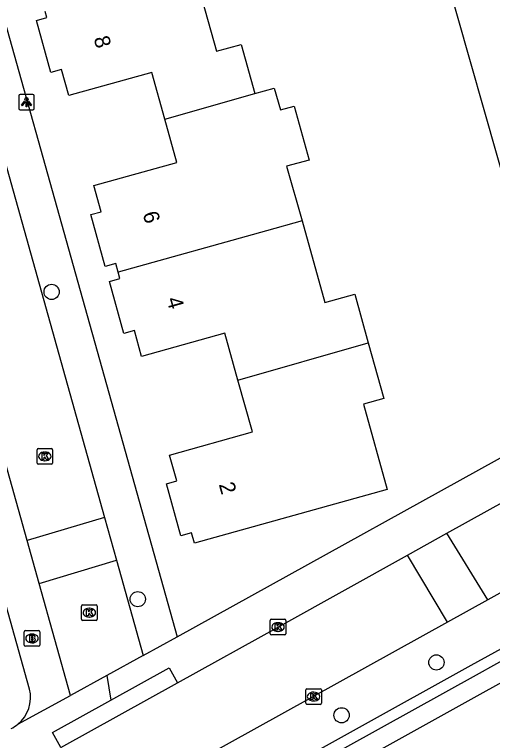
# Model space of a CAD drawing. Extents: x 159628 to 160723, y 388176 to 389416.
# Drawn here: x 160064 to 160094.67, y 388427.86 to 388474.45 of the extents above; entities that cross this region are included whole.
import ezdxf

# ---------------------------------------------------------------- set-up
doc = ezdxf.new("R2010")
doc.units = 0
for name, color, linetype in [('IMGEO_Boom', 7, 'Continuous'), ('IMGEO_Brandkraan', 7, 'Continuous'), ('IMGEO_Groenvoorziening', 7, 'Continuous'), ('IMGEO_Haag', 7, 'Continuous'), ('IMGEO_Kolk', 7, 'Continuous'), ('IMGEO_Lichtpunt', 7, 'Continuous'), ('IMGEO_Muur', 7, 'Continuous'), ('IMGEO_Pand', 7, 'Continuous'), ('IMGEO_Pand_nummerreeks', 7, 'Continuous'), ('IMGEO_Rijbaan_lokaal_open', 7, 'Continuous'), ('IMGEO_Voetpad_open', 7, 'Continuous')]:
    doc.layers.add(name, color=color, linetype=linetype)

msp = doc.modelspace()

# ---------------------------------------------------------------- linework, layer by layer
at = {"layer": 'IMGEO_Boom'}
for centre in [(160066.378, 388456.646), (160071.906, 388436.928), (160091.07, 388432.869), (160084.986, 388429.476)]:
    msp.add_circle(centre, 0.489, dxfattribs=at)
at = {"layer": 'IMGEO_Brandkraan'}
for p, q in [((160064.617, 388433.981), (160064.617, 388434.833)), ((160064.692, 388434.907), (160065.544, 388434.907)), ((160065.105, 388434.687), (160065.13, 388434.687)), ((160065.618, 388434.833), (160065.618, 388433.981)), ((160065.544, 388433.907), (160064.692, 388433.907)), ((160065.128, 388434.127), (160065.103, 388434.127))]:
    msp.add_line(p, q, dxfattribs=at)
for points in [[(160064.617, 388433.981), (160064.617, 388434.833)], [(160064.692, 388434.907), (160065.544, 388434.907)], [(160064.965, 388434.607), (160064.965, 388434.207), (160065.178, 388434.207)], [(160065.196, 388434.607), (160064.965, 388434.607)], [(160065.618, 388434.833), (160065.618, 388433.981)], [(160065.144, 388434.526), (160065.09, 388434.526), (160065.09, 388434.45)], [(160065.09, 388434.45), (160065.143, 388434.45)], [(160065.152, 388434.374), (160065.09, 388434.374), (160065.09, 388434.293)], [(160065.09, 388434.293), (160065.152, 388434.293)], [(160065.544, 388433.907), (160064.692, 388433.907)]]:
    msp.add_lwpolyline(points, dxfattribs=at)
for centre, radius, start, end in [((160064.694, 388434.831), 0.0765, 91.552, 178.448), ((160064.694, 388434.831), 0.0765, 91.552, 178.448), ((160065.2, 388434.462), 0.145, 59.4692, 91.5367), ((160065.542, 388434.831), 0.0765, 1.552, 88.448), ((160065.542, 388434.831), 0.0765, 1.552, 88.448), ((160065.145, 388434.488), 0.0379, 267.8285, 90.9355), ((160065.153, 388434.333), 0.0404, 269.8759, 90.5077), ((160065.184, 388434.458), 0.251, 268.6676, 293.5347), ((160065.225, 388434.509), 0.0922, 285.5137, 58.1501), ((160065.23, 388434.317), 0.105, 301.3115, 78.989), ((160064.694, 388433.983), 0.0765, 181.552, 268.448), ((160064.694, 388433.983), 0.0765, 181.552, 268.448), ((160065.542, 388433.983), 0.0765, 271.552, 358.448), ((160065.542, 388433.983), 0.0765, 271.552, 358.448)]:
    msp.add_arc(centre, radius, start, end, dxfattribs=at)
for centre, major_axis, ratio, start_param, end_param in [((160065.104, 388434.407), (-0.387, 0.002), 0.722429, 4.712389, 7.853982), ((160065.129, 388434.407), (-0.39, 0.002), 0.717154, 1.570796, 4.712389)]:
    msp.add_ellipse(centre, major_axis=major_axis, ratio=ratio, start_param=start_param, end_param=end_param, dxfattribs=at)
at = {"layer": 'IMGEO_Groenvoorziening'}
msp.add_lwpolyline([(160134.059, 388453.138), (160126.17, 388448.757), (160071.823, 388418.575), (160075.33, 388405.904)], dxfattribs=at)
at = {"layer": 'IMGEO_Haag'}
for points in [[(160070.833, 388420.227), (160093.307, 388432.688), (160095.907, 388434.13), (160127.052, 388451.4), (160127.514, 388451.656), (160133.566, 388454.936)], [(160071.028, 388419.535), (160093.647, 388432.076), (160096.247, 388433.518), (160127.392, 388450.788), (160127.85, 388451.042), (160133.756, 388454.242)]]:
    msp.add_lwpolyline(points, dxfattribs=at)
at = {"layer": 'IMGEO_Kolk'}
for p, q in [((160065.442, 388445.667), (160065.442, 388446.519)), ((160065.517, 388446.593), (160066.369, 388446.593)), ((160065.93, 388446.373), (160065.955, 388446.373)), ((160066.443, 388446.519), (160066.443, 388445.667)), ((160065.953, 388445.813), (160065.928, 388445.813)), ((160066.369, 388445.593), (160065.517, 388445.593)), ((160068.3, 388435.637), (160068.3, 388436.489)), ((160068.375, 388436.563), (160069.227, 388436.563)), ((160069.301, 388436.489), (160069.301, 388435.637)), ((160068.788, 388436.343), (160068.813, 388436.343)), ((160069.227, 388435.563), (160068.375, 388435.563)), ((160068.811, 388435.783), (160068.786, 388435.783)), ((160080.407, 388434.712), (160080.407, 388435.564)), ((160080.482, 388435.638), (160081.334, 388435.638)), ((160081.408, 388435.564), (160081.408, 388434.712)), ((160080.895, 388435.418), (160080.92, 388435.418)), ((160081.334, 388434.638), (160080.482, 388434.638)), ((160080.918, 388434.858), (160080.893, 388434.858)), ((160082.687, 388430.253), (160082.687, 388431.105)), ((160082.762, 388431.179), (160083.614, 388431.179)), ((160083.175, 388430.959), (160083.2, 388430.959)), ((160083.688, 388431.105), (160083.688, 388430.253)), ((160083.614, 388430.179), (160082.762, 388430.179)), ((160083.198, 388430.399), (160083.173, 388430.399))]:
    msp.add_line(p, q, dxfattribs=at)
for points in [[(160065.442, 388445.667), (160065.442, 388446.519)], [(160065.517, 388446.593), (160066.369, 388446.593)], [(160065.763, 388446.293), (160065.886, 388446.293), (160065.886, 388446.142), (160066.016, 388446.293), (160066.18, 388446.293), (160066.034, 388446.142), (160066.187, 388445.893), (160066.035, 388445.893), (160065.95, 388446.057), (160065.886, 388445.99), (160065.886, 388445.893), (160065.763, 388445.893), (160065.763, 388446.293)], [(160066.443, 388446.519), (160066.443, 388445.667)], [(160066.369, 388445.593), (160065.517, 388445.593)], [(160068.3, 388435.637), (160068.3, 388436.489)], [(160068.375, 388436.563), (160069.227, 388436.563)], [(160069.301, 388436.489), (160069.301, 388435.637)], [(160068.621, 388436.263), (160068.744, 388436.263), (160068.744, 388436.112), (160068.874, 388436.263), (160069.038, 388436.263), (160068.892, 388436.112), (160069.045, 388435.863), (160068.893, 388435.863), (160068.808, 388436.027), (160068.744, 388435.96), (160068.744, 388435.863), (160068.621, 388435.863), (160068.621, 388436.263)], [(160069.227, 388435.563), (160068.375, 388435.563)], [(160080.407, 388434.712), (160080.407, 388435.564)], [(160080.482, 388435.638), (160081.334, 388435.638)], [(160081.408, 388435.564), (160081.408, 388434.712)], [(160080.728, 388435.338), (160080.851, 388435.338), (160080.851, 388435.187), (160080.981, 388435.338), (160081.145, 388435.338), (160080.999, 388435.187), (160081.152, 388434.938), (160081, 388434.938), (160080.915, 388435.102), (160080.851, 388435.035), (160080.851, 388434.938), (160080.728, 388434.938), (160080.728, 388435.338)], [(160081.334, 388434.638), (160080.482, 388434.638)], [(160082.687, 388430.253), (160082.687, 388431.105)], [(160082.762, 388431.179), (160083.614, 388431.179)], [(160083.008, 388430.879), (160083.131, 388430.879), (160083.131, 388430.728), (160083.261, 388430.879), (160083.425, 388430.879), (160083.279, 388430.728), (160083.432, 388430.479), (160083.28, 388430.479), (160083.195, 388430.643), (160083.131, 388430.576), (160083.131, 388430.479), (160083.008, 388430.479), (160083.008, 388430.879)], [(160083.688, 388431.105), (160083.688, 388430.253)], [(160083.614, 388430.179), (160082.762, 388430.179)]]:
    msp.add_lwpolyline(points, dxfattribs=at)
for centre, start, end in [((160065.519, 388446.517), 91.552, 178.448), ((160065.519, 388446.517), 91.552, 178.448), ((160066.367, 388446.517), 1.552, 88.448), ((160066.367, 388446.517), 1.552, 88.448), ((160065.519, 388445.669), 181.552, 268.448), ((160065.519, 388445.669), 181.552, 268.448), ((160066.367, 388445.669), 271.552, 358.448), ((160066.367, 388445.669), 271.552, 358.448), ((160068.377, 388436.487), 91.552, 178.448), ((160068.377, 388436.487), 91.552, 178.448), ((160069.225, 388436.487), 1.552, 88.448), ((160069.225, 388436.487), 1.552, 88.448), ((160068.377, 388435.639), 181.552, 268.448), ((160068.377, 388435.639), 181.552, 268.448), ((160069.225, 388435.639), 271.552, 358.448), ((160069.225, 388435.639), 271.552, 358.448), ((160080.484, 388435.562), 91.552, 178.448), ((160080.484, 388435.562), 91.552, 178.448), ((160081.332, 388435.562), 1.552, 88.448), ((160081.332, 388435.562), 1.552, 88.448), ((160080.484, 388434.714), 181.552, 268.448), ((160080.484, 388434.714), 181.552, 268.448), ((160081.332, 388434.714), 271.552, 358.448), ((160081.332, 388434.714), 271.552, 358.448), ((160082.764, 388431.103), 91.552, 178.448), ((160082.764, 388431.103), 91.552, 178.448), ((160083.612, 388431.103), 1.552, 88.448), ((160083.612, 388431.103), 1.552, 88.448), ((160082.764, 388430.255), 181.552, 268.448), ((160082.764, 388430.255), 181.552, 268.448), ((160083.612, 388430.255), 271.552, 358.448), ((160083.612, 388430.255), 271.552, 358.448)]:
    msp.add_arc(centre, 0.0765, start, end, dxfattribs=at)
for centre, major_axis, ratio, start_param, end_param in [((160065.929, 388446.093), (-0.387, 0.002), 0.722429, 4.712389, 7.853982), ((160065.954, 388446.093), (-0.39, 0.002), 0.717154, 1.570796, 4.712389), ((160068.787, 388436.063), (-0.387, 0.002), 0.722429, 4.712389, 7.853982), ((160068.812, 388436.063), (-0.39, 0.002), 0.717154, 1.570796, 4.712389), ((160080.894, 388435.138), (-0.387, 0.002), 0.722429, 4.712389, 7.853982), ((160080.919, 388435.138), (-0.39, 0.002), 0.717154, 1.570796, 4.712389), ((160083.174, 388430.679), (-0.387, 0.002), 0.722429, 4.712389, 7.853982), ((160083.199, 388430.679), (-0.39, 0.002), 0.717154, 1.570796, 4.712389)]:
    msp.add_ellipse(centre, major_axis=major_axis, ratio=ratio, start_param=start_param, end_param=end_param, dxfattribs=at)
at = {"layer": 'IMGEO_Lichtpunt'}
for p, q in [((160064.268, 388469.225), (160064.268, 388468.418)), ((160064.268, 388469.225), (160064.268, 388468.418)), ((160065.17, 388469.32), (160064.362, 388469.32)), ((160065.17, 388469.32), (160064.362, 388469.32)), ((160065.264, 388468.418), (160065.264, 388469.225)), ((160065.264, 388468.418), (160065.264, 388469.225)), ((160064.362, 388468.324), (160065.17, 388468.324)), ((160064.362, 388468.324), (160065.17, 388468.324))]:
    msp.add_line(p, q, dxfattribs=at)
for points in [[(160064.642, 388468.889), (160064.681, 388468.861), (160064.493, 388468.599), (160064.455, 388468.626), (160064.642, 388468.889)], [(160064.744, 388468.841), (160064.791, 388468.841), (160064.791, 388468.519), (160064.744, 388468.519), (160064.744, 388468.841)], [(160064.854, 388468.861), (160064.892, 388468.888), (160065.079, 388468.626), (160065.04, 388468.598), (160064.854, 388468.861)]]:
    msp.add_lwpolyline(points, dxfattribs=at)
msp.add_circle((160064.767, 388469.023), 0.0994, dxfattribs=at)
for centre, start, end in [((160064.362, 388469.225), 90, 180), ((160064.362, 388469.225), 90, 180), ((160065.17, 388469.225), 0, 90), ((160065.17, 388469.225), 0, 90), ((160064.362, 388468.418), 180, 270), ((160064.362, 388468.418), 180, 270), ((160065.17, 388468.418), 270, 0), ((160065.17, 388468.418), 270, 360)]:
    msp.add_arc(centre, 0.0946, start, end, dxfattribs=at)
at = {"layer": 'IMGEO_Muur'}
msp.add_lwpolyline([(160097.525, 388456.458), (160084.795, 388501.192)], dxfattribs=at)
at = {"layer": 'IMGEO_Pand'}
for points in [[(160075.509, 388477.292), (160076.957, 388472.092), (160078.547, 388472.535), (160079.425, 388469.382)], [(160073.636, 388467.739), (160072.804, 388470.727), (160067.476, 388469.244), (160067.01, 388470.919), (160066.335, 388470.731), (160065.407, 388474.062), (160066.081, 388474.249), (160065.973, 388474.634)], [(160079.425, 388469.382), (160080.669, 388469.728), (160081.066, 388468.334), (160081.933, 388468.575), (160082.898, 388465.107), (160081.451, 388464.711), (160082.452, 388461.218)], [(160073.636, 388467.739), (160079.425, 388469.382)], [(160070.642, 388457.914), (160070.489, 388458.463), (160069.815, 388458.275), (160068.887, 388461.606), (160069.561, 388461.793), (160069.092, 388463.478), (160074.41, 388464.957), (160073.636, 388467.739)], [(160082.452, 388461.218), (160080.163, 388460.578), (160070.642, 388457.914)], [(160082.452, 388461.218), (160083.914, 388455.969), (160085.825, 388456.501), (160086.695, 388453.375)], [(160078.336, 388450.985), (160077.49, 388453.996), (160072.153, 388452.496), (160071.687, 388454.171), (160071.012, 388453.983), (160070.084, 388457.314), (160070.758, 388457.501), (160070.642, 388457.914)], [(160086.695, 388453.375), (160087.689, 388449.806), (160086.389, 388449.445), (160087.916, 388443.96), (160075.543, 388440.516), (160075.353, 388441.189), (160074.679, 388440.999), (160073.743, 388444.33), (160074.416, 388444.519), (160073.951, 388446.174), (160079.268, 388447.667), (160078.336, 388450.985)], [(160078.336, 388450.985), (160086.695, 388453.375)]]:
    msp.add_lwpolyline(points, dxfattribs=at)
at = {"layer": 'IMGEO_Rijbaan_lokaal_open'}
for points in [[(160099.774, 388448.551), (160097.525, 388456.458), (160084.795, 388501.192)], [(160055.946, 388491.534), (160069.781, 388442.163)], [(160064.814, 388440.692), (160050.975, 388490.162)], [(160132.71, 388458.055), (160126, 388454.418), (160094.379, 388436.885)], [(160091.748, 388441.158), (160099.494, 388445.461)], [(160069.781, 388442.163), (160064.814, 388440.692)], [(160069.781, 388442.163), (160070.546, 388439.435)], [(160089.213, 388439.75), (160091.748, 388441.158)], [(160094.379, 388436.885), (160091.748, 388441.158)], [(160065.586, 388437.929), (160064.814, 388440.692)], [(160074.447, 388431.557), (160081.031, 388435.205), (160089.213, 388439.75)], [(160091.779, 388435.443), (160089.213, 388439.75)], [(160065.586, 388437.929), (160070.546, 388439.435)], [(160070.546, 388439.435), (160072.262, 388433.311)], [(160067.596, 388430.745), (160065.586, 388437.929)], [(160094.379, 388436.885), (160091.779, 388435.443)], [(160091.779, 388435.443), (160070.678, 388423.743)], [(160072.262, 388433.311), (160069.929, 388432.028)], [(160070.172, 388430.447), (160073.914, 388432.519), (160074.447, 388431.557)], [(160069.929, 388432.028), (160067.596, 388430.745)], [(160066.962, 388427.413), (160074.447, 388431.557)], [(160066.962, 388427.413), (160066.429, 388428.375), (160070.172, 388430.447)]]:
    msp.add_lwpolyline(points, dxfattribs=at)
at = {"layer": 'IMGEO_Voetpad_open'}
for points in [[(160051.036, 388517.975), (160056.074, 388500), (160074.428, 388434.513)], [(160064.967, 388431.158), (160045.697, 388500), (160042.053, 388513.017)], [(160074.428, 388434.513), (160099.774, 388448.551)], [(160072.262, 388433.311), (160074.428, 388434.513)], [(160069.929, 388432.028), (160070.172, 388430.447)], [(160064.211, 388428.899), (160067.596, 388430.745)]]:
    msp.add_lwpolyline(points, dxfattribs=at)
for centre, radius, start, end in [((160062.774, 388430.636), 2.254, 309.6008, 13.3924), ((160062.8, 388430.595), 2.206, 296.4495, 309.7487)]:
    msp.add_arc(centre, radius, start, end, dxfattribs=at)

# ---------------------------------------------------------------- texts
at = {"layer": 'IMGEO_Pand_nummerreeks'}
for s, rotation, p in [('8', 285.5747, (160069.066, 388472.927)), ('6', 285.5747, (160072.211, 388461.674)), ('4', 285.5728, (160073.741, 388456.183)), ('2', 285.7151, (160077.098, 388444.294))]:
    msp.add_text(s, height=1, rotation=rotation, dxfattribs=at).set_placement(p)

doc.saveas('drawing.dxf')
